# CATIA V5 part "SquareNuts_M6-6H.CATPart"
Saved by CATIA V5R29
Part number: SquareNuts_M6-6H
Source: Unknown
Bounding box of the stored display mesh (mm): x -7 to 7, y -7 to 7, z -3 to 3
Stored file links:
  C:\가치같이\SmartFactory_BoxErectorConveyor\Boxing(under)\SquareNuts_M6-6H.CATPart
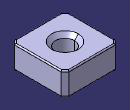
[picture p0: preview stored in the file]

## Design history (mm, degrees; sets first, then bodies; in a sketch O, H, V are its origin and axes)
Body1 (main body)
  Solid1 "PartBody": solid without history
